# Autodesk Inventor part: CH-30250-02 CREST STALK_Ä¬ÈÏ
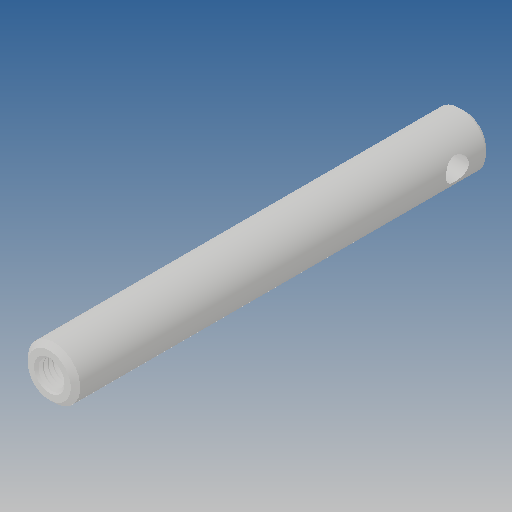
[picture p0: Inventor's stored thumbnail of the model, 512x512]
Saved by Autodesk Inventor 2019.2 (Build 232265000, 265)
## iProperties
Created: 2010-06
Part Number: CH-30250-02 CREST STALK_Ä¬ÈÏ
Material: Ogólny
Document SubType Name: Modeling
Designer: CADENGINEERING4
Density: 1 g/cm^3
Appearance: Domyślna
Author: CADENGINEERING4
Revision Number: ÈÎºÎ
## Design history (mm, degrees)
feature "NONE"
node "Bryła1"
